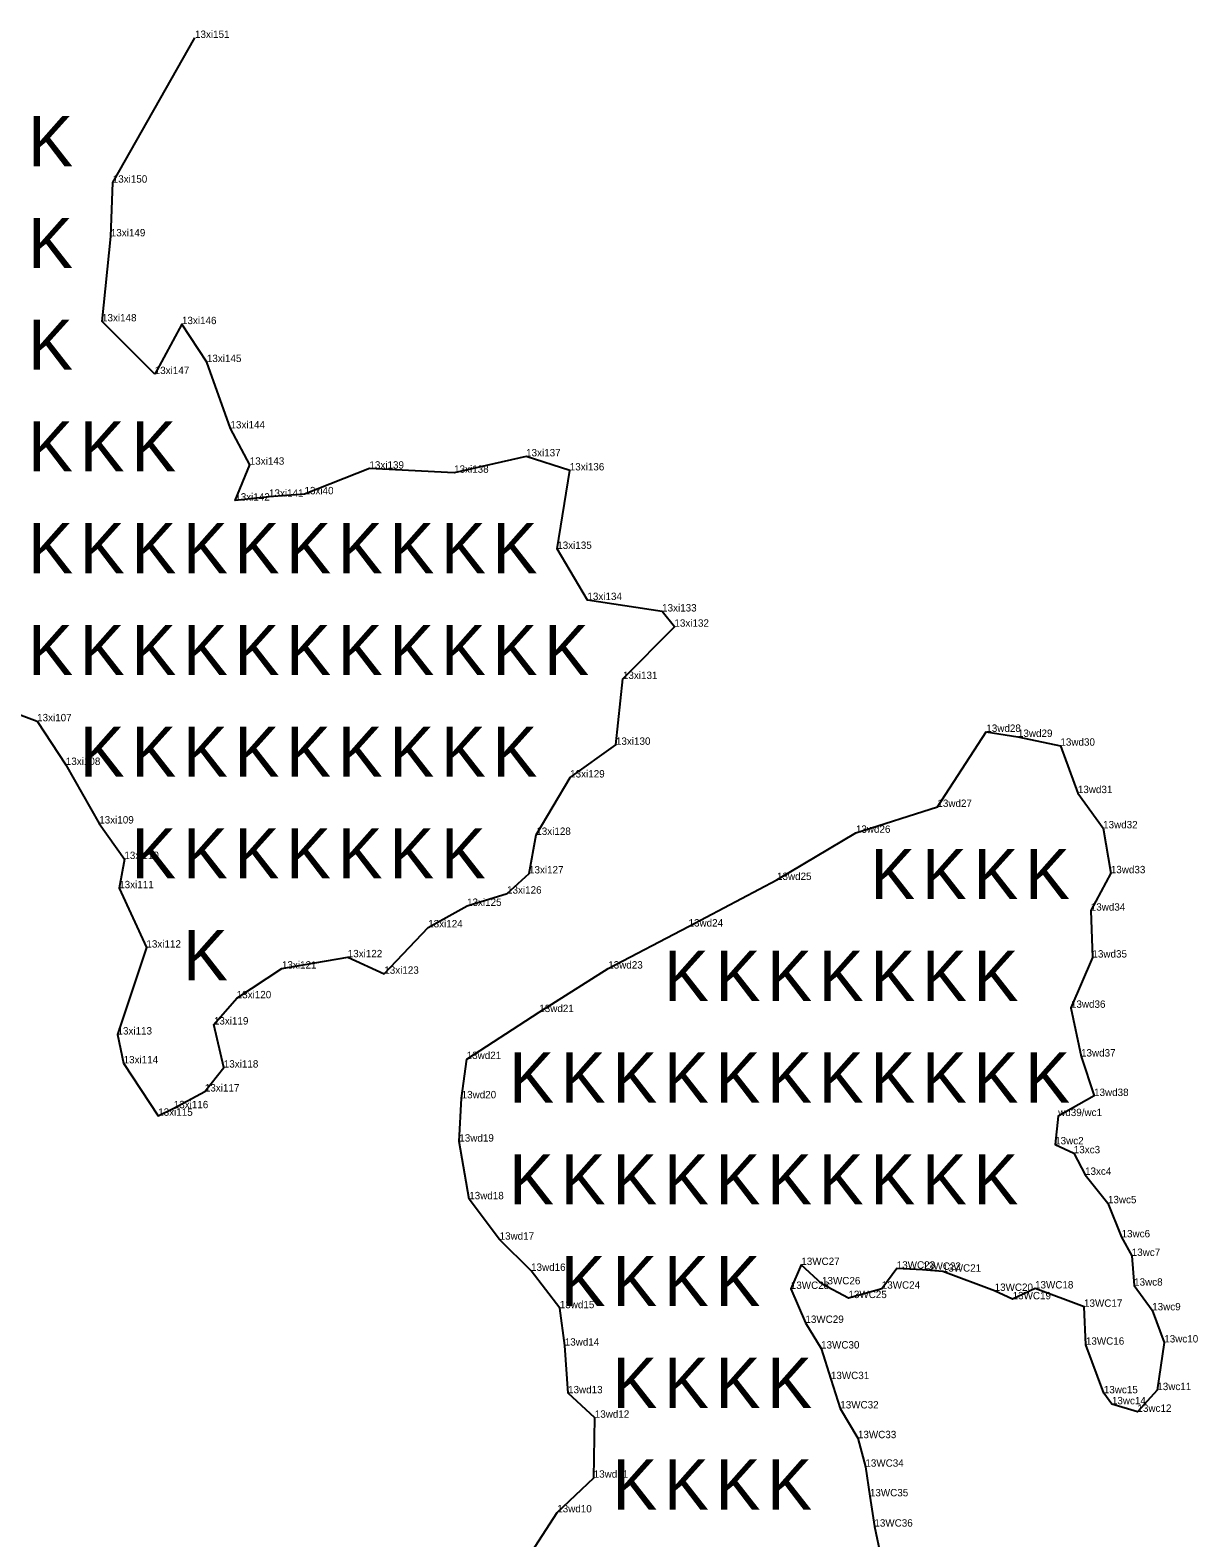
# Model space of a CAD drawing. Extents: x 2072529 to 2268812, y 436423 to 470008.
# Drawn here: x 2249752 to 2250544, y 445372 to 446395 of the extents above; entities that cross this region are included whole.
import ezdxf

# ---------------------------------------------------------------- set-up
doc = ezdxf.new("R2010")
doc.units = 0
for name, color, linetype in [('Old_Level_20', 7, 'Continuous'), ('Old_Level_52', 7, 'Continuous'), ('Old_Level_55', 7, 'Continuous'), ('Old_Level_60', 7, 'Continuous')]:
    doc.layers.add(name, color=color, linetype=linetype)

msp = doc.modelspace()

# ---------------------------------------------------------------- linework, layer by layer
at = {"layer": 'Old_Level_20'}
for p, q in [((2249864.054, 446389.51), (2249864.054, 446389.51)), ((2249808.263, 446291.367), (2249808.263, 446291.367)), ((2249806.952, 446254.92), (2249806.952, 446254.92)), ((2249800.992, 446197.275), (2249800.992, 446197.275)), ((2249855.211, 446195.401), (2249855.211, 446195.401)), ((2249836.743, 446161.549), (2249836.743, 446161.549)), ((2249872.104, 446169.706), (2249872.104, 446169.706)), ((2249888.108, 446124.67), (2249888.108, 446124.67)), ((2250088.644, 446105.724), (2250088.644, 446105.724)), ((2249901.206, 446100.088), (2249901.206, 446100.088)), ((2249982.375, 446097.438), (2249982.375, 446097.438)), ((2250039.816, 446094.602), (2250039.816, 446094.602)), ((2250118.26, 446096.199), (2250118.26, 446096.199)), ((2249938.334, 446080.021), (2249938.334, 446080.021)), ((2249891.368, 446075.752), (2249891.368, 446075.752)), ((2249914.268, 446078.351), (2249914.268, 446078.351)), ((2250109.758, 446042.981), (2250109.758, 446042.981)), ((2250130.226, 446008.305), (2250130.226, 446008.305)), ((2250180.892, 446000.528), (2250180.892, 446000.528)), ((2250189.242, 445990.208), (2250189.242, 445990.208)), ((2250154.331, 445954.77), (2250154.331, 445954.77)), ((2249756.958, 445926.078), (2249756.958, 445926.078)), ((2250400.808, 445918.894), (2250400.808, 445918.894)), ((2250149.577, 445910.129), (2250149.577, 445910.129)), ((2250422.252, 445915.472), (2250422.252, 445915.472)), ((2250451.071, 445909.522), (2250451.071, 445909.522)), ((2249776.429, 445896.462), (2249776.429, 445896.462)), ((2250118.522, 445887.955), (2250118.522, 445887.955)), ((2250462.899, 445877.362), (2250462.899, 445877.362)), ((2250367.641, 445867.985), (2250367.641, 445867.985)), ((2249799.095, 445856.755), (2249799.095, 445856.755)), ((2250095.551, 445849.029), (2250095.551, 445849.029)), ((2250312.343, 445850.441), (2250312.343, 445850.441)), ((2250480.028, 445853.489), (2250480.028, 445853.489)), ((2249816.152, 445832.664), (2249816.152, 445832.664)), ((2250090.612, 445822.894), (2250090.612, 445822.894)), ((2250258.827, 445818.467), (2250258.827, 445818.467)), ((2250485.256, 445823.027), (2250485.256, 445823.027)), ((2249812.635, 445812.868), (2249812.635, 445812.868)), ((2250075.707, 445809.205), (2250075.707, 445809.205)), ((2250048.591, 445800.888), (2250048.591, 445800.888)), ((2250471.66, 445797.663), (2250471.66, 445797.663)), ((2250022.224, 445786.308), (2250022.224, 445786.308)), ((2250198.833, 445786.89), (2250198.833, 445786.89)), ((2249831.1, 445772.602), (2249831.1, 445772.602)), ((2249967.659, 445766.044), (2249967.659, 445766.044)), ((2250472.787, 445765.849), (2250472.787, 445765.849)), ((2249923.047, 445758.366), (2249923.047, 445758.366)), ((2249992.453, 445754.848), (2249992.453, 445754.848)), ((2250144.364, 445758.387), (2250144.364, 445758.387)), ((2249892.349, 445738.224), (2249892.349, 445738.224)), ((2250097.596, 445728.876), (2250097.596, 445728.876)), ((2250458.197, 445731.761), (2250458.197, 445731.761)), ((2249811.487, 445713.658), (2249811.487, 445713.658)), ((2249876.876, 445720.427), (2249876.876, 445720.427)), ((2249815.634, 445694.123), (2249815.634, 445694.123)), ((2249883.596, 445691.254), (2249883.596, 445691.254)), ((2250048.349, 445697.048), (2250048.349, 445697.048)), ((2250465.048, 445698.73), (2250465.048, 445698.73)), ((2249870.754, 445675.001), (2249870.754, 445675.001)), ((2250473.878, 445671.975), (2250473.878, 445671.975)), ((2249849.636, 445663.68), (2249849.636, 445663.68)), ((2250044.926, 445670.395), (2250044.926, 445670.395)), ((2249839.095, 445658.543), (2249839.095, 445658.543)), ((2250449.561, 445658.346), (2250449.561, 445658.346)), ((2250043.337, 445641.028), (2250043.337, 445641.028)), ((2250447.503, 445639.154), (2250447.503, 445639.154)), ((2250460.153, 445633.119), (2250460.153, 445633.119)), ((2250467.761, 445618.475), (2250467.761, 445618.475)), ((2250050.081, 445601.94), (2250050.081, 445601.94)), ((2250483.307, 445599.234), (2250483.307, 445599.234)), ((2250070.663, 445574.539), (2250070.663, 445574.539)), ((2250492.548, 445576.113), (2250492.548, 445576.113)), ((2250499.436, 445563.489), (2250499.436, 445563.489)), ((2250092.011, 445553.379), (2250092.011, 445553.379)), ((2250275.304, 445557.376), (2250275.304, 445557.376)), ((2250340.03, 445554.884), (2250340.03, 445554.884)), ((2250357.553, 445554.082), (2250357.553, 445554.082)), ((2250371.29, 445552.832), (2250371.29, 445552.832)), ((2250268.196, 445541.116), (2250268.196, 445541.116)), ((2250289.359, 445544.245), (2250289.359, 445544.245)), ((2250329.879, 445541.272), (2250329.879, 445541.272)), ((2250406.433, 445539.779), (2250406.433, 445539.779)), ((2250433.848, 445541.429), (2250433.848, 445541.429)), ((2250501.071, 445543.349), (2250501.071, 445543.349)), ((2250111.517, 445528.038), (2250111.517, 445528.038)), ((2250307.285, 445534.902), (2250307.285, 445534.902)), ((2250418.659, 445534.094), (2250418.659, 445534.094)), ((2250467.078, 445529.007), (2250467.078, 445529.007)), ((2250278.091, 445518.097), (2250278.091, 445518.097)), ((2250513.323, 445526.62), (2250513.323, 445526.62)), ((2250114.867, 445502.675), (2250114.867, 445502.675)), ((2250288.716, 445500.696), (2250288.716, 445500.696)), ((2250468.341, 445503.313), (2250468.341, 445503.313)), ((2250521.505, 445504.804), (2250521.505, 445504.804)), ((2250295.375, 445479.962), (2250295.375, 445479.962)), ((2250117.098, 445470.353), (2250117.098, 445470.353)), ((2250480.512, 445470.342), (2250480.512, 445470.342)), ((2250516.789, 445472.496), (2250516.789, 445472.496)), ((2250301.746, 445460.062), (2250301.746, 445460.062)), ((2250485.992, 445462.892), (2250485.992, 445462.892)), ((2250503.336, 445457.758), (2250503.336, 445457.758)), ((2250135.235, 445453.754), (2250135.235, 445453.754)), ((2250313.716, 445439.903), (2250313.716, 445439.903)), ((2250318.777, 445420.55), (2250318.777, 445420.55)), ((2250134.485, 445413.117), (2250134.485, 445413.117)), ((2250321.832, 445400.469), (2250321.832, 445400.469)), ((2250109.769, 445389.585), (2250109.769, 445389.585)), ((2250324.878, 445379.928), (2250324.878, 445379.928))]:
    msp.add_line(p, q, dxfattribs=at)
at = {"layer": 'Old_Level_52'}
for points in [[(2249836.743, 446161.549), (2249800.992, 446197.275), (2249806.952, 446254.92), (2249808.263, 446291.367), (2249864.054, 446389.51)], [(2249726.667, 445937.537), (2249756.958, 445926.078), (2249776.429, 445896.462), (2249799.095, 445856.755), (2249816.152, 445832.664), (2249812.635, 445812.868), (2249831.1, 445772.602), (2249811.487, 445713.658), (2249815.634, 445694.123), (2249839.095, 445658.543), (2249849.636, 445663.68), (2249870.754, 445675.001), (2249883.596, 445691.254), (2249876.876, 445720.427), (2249892.349, 445738.224), (2249923.047, 445758.366), (2249967.659, 445766.044), (2249992.453, 445754.848), (2250022.224, 445786.308), (2250048.591, 445800.888), (2250075.707, 445809.205), (2250090.612, 445822.894), (2250095.551, 445849.029), (2250118.522, 445887.955), (2250149.577, 445910.129), (2250154.331, 445954.77), (2250189.242, 445990.208), (2250180.892, 446000.528), (2250130.226, 446008.305), (2250109.758, 446042.981), (2250118.26, 446096.199), (2250088.644, 446105.724), (2250039.816, 446094.602), (2249982.375, 446097.438), (2249938.334, 446080.021), (2249914.268, 446078.351), (2249891.368, 446075.752), (2249901.206, 446100.088), (2249888.108, 446124.67), (2249872.104, 446169.706), (2249855.211, 446195.401), (2249836.743, 446161.549)], [(2250072.796, 445332.468), (2250109.769, 445389.585), (2250134.485, 445413.117), (2250135.235, 445453.754), (2250117.098, 445470.353), (2250114.867, 445502.675), (2250111.517, 445528.038), (2250092.011, 445553.379), (2250070.663, 445574.539), (2250050.081, 445601.94), (2250043.337, 445641.028), (2250044.926, 445670.395), (2250048.349, 445697.048), (2250097.596, 445728.876), (2250144.364, 445758.387), (2250198.833, 445786.89), (2250258.827, 445818.467), (2250312.343, 445850.441), (2250367.641, 445867.985), (2250400.808, 445918.894), (2250422.252, 445915.472), (2250451.071, 445909.522), (2250462.899, 445877.362), (2250480.028, 445853.489), (2250485.256, 445823.027), (2250471.66, 445797.663), (2250472.787, 445765.849), (2250458.197, 445731.761), (2250465.048, 445698.73), (2250473.878, 445671.975), (2250449.561, 445658.346), (2250447.503, 445639.154), (2250460.153, 445633.119), (2250467.761, 445618.475), (2250483.307, 445599.234), (2250492.548, 445576.113), (2250499.436, 445563.489), (2250501.071, 445543.349), (2250513.323, 445526.62), (2250521.505, 445504.804), (2250516.789, 445472.496), (2250503.336, 445457.758), (2250485.992, 445462.892), (2250480.512, 445470.342), (2250468.341, 445503.313), (2250467.078, 445529.007), (2250433.848, 445541.429), (2250418.659, 445534.094), (2250406.433, 445539.779), (2250371.29, 445552.832), (2250357.553, 445554.082), (2250340.03, 445554.884), (2250329.879, 445541.272), (2250307.285, 445534.902), (2250289.359, 445544.245), (2250275.304, 445557.376), (2250268.196, 445541.116), (2250278.091, 445518.097), (2250288.716, 445500.696), (2250295.375, 445479.962), (2250301.746, 445460.062), (2250313.716, 445439.903), (2250318.777, 445420.55), (2250321.832, 445400.469), (2250324.878, 445379.928), (2250329.288, 445359.697)]]:
    msp.add_lwpolyline(points, dxfattribs=at)

# ---------------------------------------------------------------- texts
at = {"layer": 'Old_Level_55'}
for p in [(2249750.96, 446302.486), (2249750.96, 446233.486), (2249750.96, 446164.486), (2249750.96, 446095.486), (2249785.96, 446095.486), (2249820.96, 446095.486), (2249750.96, 446026.486), (2249785.96, 446026.486), (2249820.96, 446026.486), (2249855.96, 446026.486), (2249890.96, 446026.486), (2249925.96, 446026.486), (2249960.96, 446026.486), (2249995.96, 446026.486), (2250030.96, 446026.486), (2250065.96, 446026.486), (2249750.96, 445957.486), (2249785.96, 445957.486), (2249820.96, 445957.486), (2249855.96, 445957.486), (2249890.96, 445957.486), (2249925.96, 445957.486), (2249960.96, 445957.486), (2249995.96, 445957.486), (2250030.96, 445957.486), (2250065.96, 445957.486), (2250100.96, 445957.486), (2249785.96, 445888.486), (2249820.96, 445888.486), (2249855.96, 445888.486), (2249890.96, 445888.486), (2249925.96, 445888.486), (2249960.96, 445888.486), (2249995.96, 445888.486), (2250030.96, 445888.486), (2250065.96, 445888.486), (2249820.96, 445819.486), (2249855.96, 445819.486), (2249890.96, 445819.486), (2249925.96, 445819.486), (2249960.96, 445819.486), (2249995.96, 445819.486), (2250030.96, 445819.486), (2250322.194, 445805.483), (2250357.194, 445805.483), (2250392.194, 445805.483), (2250427.194, 445805.483), (2249855.96, 445750.486), (2250182.194, 445736.483), (2250217.194, 445736.483), (2250252.194, 445736.483), (2250287.194, 445736.483), (2250322.194, 445736.483), (2250357.194, 445736.483), (2250392.194, 445736.483), (2250077.194, 445667.483), (2250112.194, 445667.483), (2250147.194, 445667.483), (2250182.194, 445667.483), (2250217.194, 445667.483), (2250252.194, 445667.483), (2250287.194, 445667.483), (2250322.194, 445667.483), (2250357.194, 445667.483), (2250392.194, 445667.483), (2250427.194, 445667.483), (2250077.194, 445598.483), (2250112.194, 445598.483), (2250147.194, 445598.483), (2250182.194, 445598.483), (2250217.194, 445598.483), (2250252.194, 445598.483), (2250287.194, 445598.483), (2250322.194, 445598.483), (2250357.194, 445598.483), (2250392.194, 445598.483), (2250112.194, 445529.483), (2250147.194, 445529.483), (2250182.194, 445529.483), (2250217.194, 445529.483), (2250147.194, 445460.483), (2250182.194, 445460.483), (2250217.194, 445460.483), (2250252.194, 445460.483), (2250147.194, 445391.483), (2250182.194, 445391.483), (2250217.194, 445391.483), (2250252.194, 445391.483)]:
    msp.add_text('K', height=34, dxfattribs=at).set_placement(p)
at = {"layer": 'Old_Level_60'}
for s, p in [('13xi151', (2249864.054, 446389.51)), ('13xi150', (2249808.263, 446291.367)), ('13xi149', (2249806.952, 446254.92)), ('13xi148', (2249800.992, 446197.275)), ('13xi146', (2249855.211, 446195.401)), ('13xi145', (2249872.104, 446169.706)), ('13xi147', (2249836.743, 446161.549)), ('13xi144', (2249888.108, 446124.67)), ('13xi137', (2250088.644, 446105.724)), ('13xi143', (2249901.206, 446100.088)), ('13xi139', (2249982.375, 446097.438)), ('13xi136', (2250118.26, 446096.199)), ('13xi138', (2250039.816, 446094.602)), ('13xi142', (2249891.368, 446075.752)), ('13xi141', (2249914.268, 446078.351)), ('13xi40', (2249938.334, 446080.021)), ('13xi135', (2250109.758, 446042.981)), ('13xi134', (2250130.226, 446008.305)), ('13xi133', (2250180.892, 446000.528)), ('13xi132', (2250189.242, 445990.208)), ('13xi131', (2250154.331, 445954.77)), ('13xi107', (2249756.958, 445926.078)), ('13wd28', (2250400.808, 445918.894)), ('13wd29', (2250422.252, 445915.472)), ('13xi130', (2250149.577, 445910.129)), ('13wd30', (2250451.071, 445909.522)), ('13xi108', (2249776.429, 445896.462)), ('13xi129', (2250118.522, 445887.955)), ('13wd31', (2250462.899, 445877.362)), ('13wd27', (2250367.641, 445867.985)), ('13xi109', (2249799.095, 445856.755)), ('13wd26', (2250312.343, 445850.441)), ('13wd32', (2250480.028, 445853.489)), ('13xi128', (2250095.551, 445849.029)), ('13xi110', (2249816.152, 445832.664)), ('13xi127', (2250090.612, 445822.894)), ('13wd33', (2250485.256, 445823.027)), ('13xi111', (2249812.635, 445812.868)), ('13xi126', (2250075.707, 445809.205)), ('13wd25', (2250258.827, 445818.467)), ('13xi125', (2250048.591, 445800.888)), ('13wd34', (2250471.66, 445797.663)), ('13xi124', (2250022.224, 445786.308)), ('13wd24', (2250198.833, 445786.89)), ('13xi112', (2249831.1, 445772.602)), ('13xi121', (2249923.047, 445758.366)), ('13xi122', (2249967.659, 445766.044)), ('13wd23', (2250144.364, 445758.387)), ('13wd35', (2250472.787, 445765.849)), ('13xi123', (2249992.453, 445754.848)), ('13xi120', (2249892.349, 445738.224)), ('13wd21', (2250097.596, 445728.876)), ('13wd36', (2250458.197, 445731.761)), ('13xi119', (2249876.876, 445720.427)), ('13xi113', (2249811.487, 445713.658)), ('13wd21', (2250048.349, 445697.048)), ('13wd37', (2250465.048, 445698.73)), ('13xi114', (2249815.634, 445694.123)), ('13xi118', (2249883.596, 445691.254)), ('13xi117', (2249870.754, 445675.001)), ('13wd20', (2250044.926, 445670.395)), ('13wd38', (2250473.878, 445671.975)), ('13xi115', (2249839.095, 445658.543)), ('13xi116', (2249849.636, 445663.68)), ('wd39/wc1', (2250449.561, 445658.346)), ('13wd19', (2250043.337, 445641.028)), ('13wc2', (2250447.503, 445639.154)), ('13xc3', (2250460.153, 445633.119)), ('13xc4', (2250467.761, 445618.475)), ('13wd18', (2250050.081, 445601.94)), ('13wc5', (2250483.307, 445599.234)), ('13wd17', (2250070.663, 445574.539)), ('13wc6', (2250492.548, 445576.113)), ('13wc7', (2250499.436, 445563.489)), ('13wd16', (2250092.011, 445553.379)), ('13WC27', (2250275.304, 445557.376)), ('13WC23', (2250340.03, 445554.884)), ('13WC22', (2250357.553, 445554.082)), ('13WC26', (2250289.359, 445544.245)), ('13WC21', (2250371.29, 445552.832)), ('13wc8', (2250501.071, 445543.349)), ('13WC28', (2250268.196, 445541.116)), ('13WC25', (2250307.285, 445534.902)), ('13WC24', (2250329.879, 445541.272)), ('13WC20', (2250406.433, 445539.779)), ('13WC19', (2250418.659, 445534.094)), ('13WC18', (2250433.848, 445541.429)), ('13wd15', (2250111.517, 445528.038)), ('13WC17', (2250467.078, 445529.007)), ('13wc9', (2250513.323, 445526.62)), ('13WC29', (2250278.091, 445518.097)), ('13wd14', (2250114.867, 445502.675)), ('13WC16', (2250468.341, 445503.313)), ('13wc10', (2250521.505, 445504.804)), ('13WC30', (2250288.716, 445500.696)), ('13WC31', (2250295.375, 445479.962)), ('13wc11', (2250516.789, 445472.496)), ('13wd13', (2250117.098, 445470.353)), ('13wc15', (2250480.512, 445470.342)), ('13wc14', (2250485.992, 445462.892)), ('13wd12', (2250135.235, 445453.754)), ('13WC32', (2250301.746, 445460.062)), ('13wc12', (2250503.336, 445457.758)), ('13WC33', (2250313.716, 445439.903)), ('13WC34', (2250318.777, 445420.55)), ('13wd11', (2250134.485, 445413.117)), ('13WC35', (2250321.832, 445400.469)), ('13wd10', (2250109.769, 445389.585)), ('13WC36', (2250324.878, 445379.928))]:
    msp.add_text(s, height=5, dxfattribs=at).set_placement(p)

doc.saveas('drawing.dxf')
